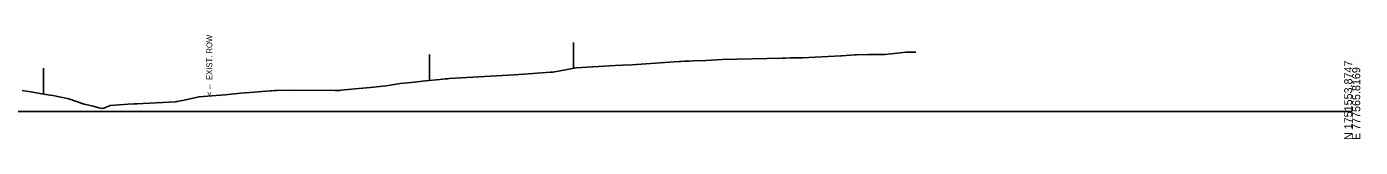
# Model space of a CAD drawing. Extents: x 776426 to 854588, y 1736205 to 1756790.
# Drawn here: x 806406.9 to 806873.6, y 1745205.1 to 1745241.4 of the extents above; entities that cross this region are included whole.
import ezdxf

# ---------------------------------------------------------------- set-up
doc = ezdxf.new("R2010")
doc.units = 0
for name, color, linetype in [('63', 7, 'Continuous'), ('DTM CONTOURS_MAJOR_TX', 7, 'Continuous'), ('DTM_X_FLOW_ARROWS', 7, 'Continuous'), ('TRANS_UNPAVED_SHOULDERS', 7, 'Continuous'), ('XS_X_ROW', 7, 'Continuous')]:
    doc.layers.add(name, color=color, linetype=linetype)

msp = doc.modelspace()

# ---------------------------------------------------------------- linework, layer by layer
at = {"layer": '63'}
msp.add_line((806412.79, 1745229.79), (806412.79, 1745220.79), dxfattribs=at)
msp.add_line((806412.79, 1745229.79), (806412.79, 1745220.79), dxfattribs=at)
at = {"layer": 'DTM CONTOURS_MAJOR_TX'}
msp.add_line((806370.79, 1745214.76), (806870.79, 1745214.76), dxfattribs=at)
at = {"layer": 'DTM_X_FLOW_ARROWS'}
msp.add_lwpolyline([(806405.31, 1745222.05), (806408.26, 1745221.62), (806413.61, 1745220.65), (806415.06, 1745220.36), (806415.96, 1745220.23), (806421.59, 1745219.17), (806426.6, 1745217.41), (806426.95, 1745217.28), (806428.63, 1745216.88), (806429.09, 1745216.79), (806429.53, 1745216.73), (806430.09, 1745216.61), (806432.13, 1745216.02), (806433.26, 1745215.71), (806433.81, 1745215.89), (806436.09, 1745216.77), (806442.39, 1745217.29), (806444.45, 1745217.4), (806445.53, 1745217.41), (806447.68, 1745217.47), (806459.1, 1745218.11), (806459.44, 1745218.15), (806461.38, 1745218.54), (806467.17, 1745219.83), (806471.67, 1745220.19), (806476.28, 1745220.57), (806481.75, 1745221.13), (806486.45, 1745221.49), (806490.58, 1745221.8), (806492.05, 1745221.91), (806492.49, 1745221.94), (806493.63, 1745221.99), (806494.41, 1745222.02), (806498.83, 1745222.18), (806514.76, 1745222), (806515.64, 1745221.98), (806516.51, 1745222.07), (806516.87, 1745222.11), (806520.59, 1745222.55), (806527.07, 1745223.13), (806532.65, 1745223.67), (806536.88, 1745224.38), (806537.56, 1745224.45), (806541.47, 1745224.87), (806546.44, 1745225.43), (806551.48, 1745225.89), (806553.32, 1745226.05), (806553.64, 1745226.1), (806554.22, 1745226.15), (806554.7, 1745226.17), (806577.46, 1745227.54), (806582.33, 1745227.87), (806584.03, 1745227.99), (806590.23, 1745228.37), (806591, 1745228.42), (806599.14, 1745229.89), (806612.88, 1745230.73), (806615.44, 1745230.86), (806618.67, 1745231.03), (806633.48, 1745231.98), (806635.34, 1745232.11), (806635.79, 1745232.13), (806637.18, 1745232.21), (806638.74, 1745232.29), (806640.15, 1745232.39), (806644.6, 1745232.53), (806650.33, 1745232.79), (806671.26, 1745233.3), (806672.5, 1745233.34), (806674.24, 1745233.37), (806678.35, 1745233.42), (806691.84, 1745234.08), (806692.33, 1745234.11), (806696.61, 1745234.43), (806697.28, 1745234.49), (806701.53, 1745234.56), (806704.26, 1745234.6), (806707.23, 1745234.64), (806711.59, 1745235.05), (806714.55, 1745235.35), (806717.77, 1745235.35), (806718.1, 1745235.36)], dxfattribs=at)
at = {"layer": 'TRANS_UNPAVED_SHOULDERS'}
for p, q in [((806598.3, 1745238.73), (806598.3, 1745229.73)), ((806598.3, 1745238.73), (806598.3, 1745229.73)), ((806547.86, 1745234.56), (806547.86, 1745225.56)), ((806547.86, 1745234.56), (806547.86, 1745225.56))]:
    msp.add_line(p, q, dxfattribs=at)

# ---------------------------------------------------------------- texts
at = {"layer": 'DTM CONTOURS_MAJOR_TX'}
for s, p in [('N 1751553.8747', (806870.79, 1745204.76)), ('E 777565.8169', (806873.59, 1745204.76))]:
    msp.add_text(s, height=2.8, rotation=90, dxfattribs=at).set_placement(p)
at = {"layer": 'XS_X_ROW'}
msp.add_text('< --  EXIST. ROW', height=2, rotation=90, dxfattribs=at).set_placement((806471.79, 1745220.12))

doc.saveas('drawing.dxf')
